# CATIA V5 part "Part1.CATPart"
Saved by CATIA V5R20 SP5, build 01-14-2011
Part number: 轴
Material "Alcantara": density 900 kg/m3
Bounding box of the stored display mesh (mm): x -50 to 50, y -50 to 50, z -50 to 50
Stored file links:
  E:\scc\Part1.CATPart
  C:\Program Files\Dassault Systemes\B20\intel_a\startup\materials\Catalog.CATMaterial
  C:\Program Files\Dassault Systemes\B20\intel_a\startup\materials\alcantara.jpg
  E:\scc\Product1.CATProduct
  Part2.CATPart
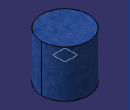
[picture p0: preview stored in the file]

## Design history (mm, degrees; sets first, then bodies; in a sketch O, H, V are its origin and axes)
External parameters (linked from other documents)
  `External.长度.1` = 50 mm
Body1 (main body), material "Alcantara"
  Sketch1 on xy-plane, origin (0, 0, 0), H (1, 0, 0), V (0, 1, 0)
    circle A1 centre (0, 0) radius 50
    radius A1 = 50 {= `External.长度.1`}
  Pad1: profile Sketch1, direction (0, 0, 1), length 50, mirrored extent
